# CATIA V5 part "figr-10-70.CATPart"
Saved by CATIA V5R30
Part number: Part1
Bounding box of the stored display mesh (mm): x -80.563 to 63.541, y -72 to 69, z -55 to 56
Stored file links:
  D:\PROJECTS\CATIA V56R 2020\Resources\Parts File\c10_catia_v5_6r2020_prt\figr-10-70.CATPart
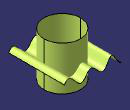
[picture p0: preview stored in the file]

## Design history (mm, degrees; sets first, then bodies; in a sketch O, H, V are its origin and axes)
Set1
  Sketch1 on xy-plane, origin (0, 0, 0), H (-1, 0, 0), V (0, -1, 0)
    circle A1 centre (0, 0) radius 45.985
  Extrude1: Element1 Sketch1, Lim1 56, Lim2 55, Direction xy-plane
  Sketch2 on zx-plane, origin (0, 0, 0), H (1, 0, 0), V (0, 0, -1)
    spline S1 through (-80.5635, 24.8913) (-73.6025, 19.8803) (-54.8525, -3.3629) (-35.1982, 19.8803) (-2.6271, -1.6506) (16.6996, 17.2854) (52.4104, -6.7877) (63.5409, 1.5862)
  Extrude2: Element1 Sketch2, Lim1 72, Lim2 69, Direction Sketch1.V
Body1 (main body)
